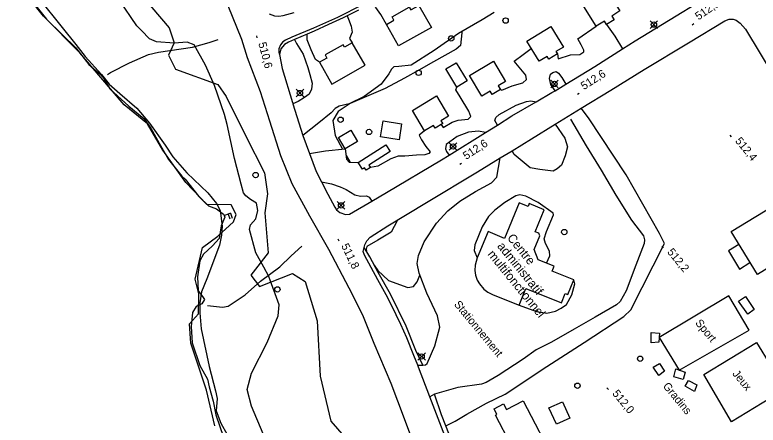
# Model space of a CAD drawing. Extents: x 347312 to 350503, y 6073086 to 6076432.
# Drawn here: x 348733 to 349011.5, y 6075010.1 to 6075163.9 of the extents above; entities that cross this region are included whole.
import ezdxf

# ---------------------------------------------------------------- set-up
doc = ezdxf.new("R2010")
doc.units = 0
for name, color, linetype in [('Level 1', 7, 'Continuous'), ('Level 19', 7, 'Continuous'), ('Level 2', 7, 'Continuous'), ('Level 21', 7, 'Continuous'), ('Level 22', 7, 'Continuous'), ('Level 26', 7, 'Continuous'), ('Level 3', 7, 'Continuous'), ('Level 31', 7, 'Continuous'), ('Level 36', 7, 'Continuous'), ('Level 37', 7, 'Continuous'), ('Level 4', 7, 'Continuous'), ('Level 44', 7, 'Continuous'), ('Level 52', 7, 'Continuous'), ('Level 56', 7, 'Continuous')]:
    doc.layers.add(name, color=color, linetype=linetype)

msp = doc.modelspace()

# ---------------------------------------------------------------- linework, layer by layer
at = {"layer": 'Level 1'}
for points in [[(348778.77, 6075159.8), (348765.55, 6075179.35)], [(348828.23, 6075065.76), (348826.31, 6075069.28), (348823.3, 6075074.72), (348820.99, 6075083.43), (348821.36, 6075085.16), (348823.3, 6075087.37), (348824.01, 6075090.6), (348823.55, 6075093.24), (348821.36, 6075094.6), (348819.6, 6075096.09), (348818.71, 6075097.18)], [(348826.08, 6075006.84), (348821.74, 6075017.15), (348820.1, 6075023.49), (348821.66, 6075029.61), (348827.51, 6075041.09), (348831.74, 6075051.08), (348832.12, 6075055.17), (348830.6, 6075059.27), (348828.86, 6075064.09), (348828.23, 6075065.76)]]:
    msp.add_lwpolyline(points, dxfattribs=at)
at = {"layer": 'Level 19'}
for points in [[(348872.23, 6075160.3), (348870.1, 6075163.96), (348868.29, 6075166.68), (348867.06, 6075168.92)], [(348912.62, 6075164.78), (348908.07, 6075162), (348899.31, 6075156.86), (348890.18, 6075150.51), (348881.47, 6075145.03), (348876.96, 6075144.47), (348875.05, 6075144.32), (348874.19, 6075143.54), (348873.21, 6075141.82), (348870.33, 6075137.93), (348863.92, 6075133.23), (348858.26, 6075130.51), (348854.59, 6075129.58), (348853.03, 6075128.74), (348851.52, 6075127.11), (348846.89, 6075123.43), (348840.91, 6075118.69)], [(348857.49, 6075163.46), (348858.02, 6075162.19), (348858.98, 6075159.59), (348859.44, 6075157.4), (348858.43, 6075154.99), (348859.47, 6075153.39)], [(348936.3, 6075149.2), (348936.56, 6075147.38), (348941.2, 6075148.88), (348944.68, 6075149.04), (348946.17, 6075150.05), (348946.27, 6075150.66), (348945.2, 6075152.68), (348943.98, 6075154.88), (348950.86, 6075159.6)], [(348954.74, 6075160.2), (348957.85, 6075155.91), (348960.72, 6075151.15)], [(348847.14, 6075146.1), (348845.71, 6075147.18), (348844.02, 6075150.75), (348842.55, 6075154.51), (348842.5, 6075156.63)], [(348837.79, 6075154.59), (348838.57, 6075153.13), (348841.05, 6075149.15), (348842.81, 6075144.13), (348843.59, 6075141.47), (348844.45, 6075138.26), (348844.16, 6075136.06), (348843.25, 6075134.17), (348841.56, 6075132.85), (348839.23, 6075131.38), (348837.2, 6075130.49)], [(348914.95, 6075135.93), (348915.52, 6075135.64), (348919.42, 6075137.29), (348923.4, 6075138.4), (348924.68, 6075139.64), (348924.5, 6075141.22), (348920.08, 6075146.53), (348923.43, 6075148.99), (348926.5, 6075151.27)], [(348935.45, 6075135.43), (348933.89, 6075137.76), (348933.32, 6075139.99), (348933.71, 6075141.6), (348934.6, 6075142.26), (348935.86, 6075142.58), (348936.77, 6075142.04), (348937.95, 6075140.34), (348939.43, 6075137.86)], [(348892.82, 6075122.77), (348893.56, 6075121.68), (348896.89, 6075123.63), (348899.15, 6075124.37), (348902.86, 6075124.8), (348903.84, 6075125.83), (348903.12, 6075127.79), (348899.9, 6075133.11), (348898.25, 6075135.81), (348898.64, 6075136.81)], [(348913.85, 6075122.58), (348912.93, 6075124.23), (348913.25, 6075125.39), (348914.54, 6075126.46), (348920.82, 6075130.07), (348924.69, 6075131.39), (348926.32, 6075131.61), (348928.37, 6075131.28)], [(348941.21, 6075124.76), (348947.07, 6075114.72), (348952.72, 6075105.65), (348958.22, 6075096.32), (348964.09, 6075086.91), (348968.55, 6075081), (348968.97, 6075079.59), (348968.89, 6075078.22), (348965.73, 6075070.09), (348962.06, 6075060.48), (348959.86, 6075056.39), (348958.4, 6075055.23), (348950.44, 6075050.58), (348942.58, 6075046.09), (348934.07, 6075041.2), (348928.4, 6075038.26), (348923.49, 6075034.88), (348914.12, 6075028.74), (348909.64, 6075026.1), (348907.93, 6075025.43), (348898.98, 6075024.24), (348890.29, 6075021.66), (348888.57, 6075020.68)], [(348886.55, 6075120.42), (348884.56, 6075118.74), (348885.43, 6075116.97), (348887.05, 6075114.48), (348888.6, 6075112.52), (348888.18, 6075111.94), (348886.64, 6075111.35), (348883.49, 6075111.23), (348879.09, 6075110.9), (348876.64, 6075110.86), (348873.95, 6075109.92), (348869.03, 6075107.13), (348866.3, 6075106.64)], [(348909.37, 6075119.76), (348906.78, 6075120.24), (348903.04, 6075119.93), (348898.76, 6075118.28), (348894.69, 6075115.29), (348894.37, 6075113.67), (348894.77, 6075112.65), (348895.71, 6075111.26)], [(348843.41, 6075111.92), (348849.46, 6075112.86), (348856.83, 6075113.61), (348857.27, 6075109.75), (348858.33, 6075108.67), (348861.65, 6075108.57)], [(348847.88, 6075101.3), (348851.62, 6075100.5), (348854.9, 6075099.37), (348857.16, 6075098.38), (348860.39, 6075096.41), (348862.57, 6075095.88), (348864.81, 6075096.08), (348865.8, 6075095.53), (348866.77, 6075094.04)]]:
    msp.add_lwpolyline(points, dxfattribs=at)
at = {"layer": 'Level 2'}
for points in [[(348742.17, 6075170.03), (348750.8, 6075159.12), (348755.85, 6075152.69), (348759.36, 6075148.3), (348765.53, 6075141.47), (348768.38, 6075137.87), (348772.33, 6075134.38), (348778.7, 6075128.92), (348783.53, 6075123.24), (348789.36, 6075115.08), (348792.21, 6075110.68), (348797.51, 6075104.6), (348805.28, 6075097.13), (348808.53, 6075093.2), (348809.95, 6075090.52), (348810.64, 6075084.72), (348810.4, 6075081.33), (348809.69, 6075077.55), (348804.99, 6075064.97), (348802.95, 6075060.07), (348802.28, 6075055.92), (348802.3, 6075052.21), (348802.83, 6075046.13), (348805.87, 6075032.06), (348808.22, 6075022.98), (348808.81, 6075020.02), (348808.47, 6075015.48)], [(348811.6, 6075126.53), (348807.82, 6075137.35), (348804.4, 6075145.01), (348800.15, 6075152.66), (348797.56, 6075153.68), (348792.74, 6075153.31), (348786.06, 6075153.81), (348783.47, 6075154.84), (348780.51, 6075158.04), (348778.77, 6075159.8)], [(348900.52, 6075157.57), (348900.52, 6075157.16), (348899.95, 6075152.32), (348898.38, 6075151.02)], [(348898.38, 6075151.02), (348889.86, 6075146.23), (348884.37, 6075143.12), (348879.06, 6075140.16), (348871.78, 6075136.32), (348858.63, 6075130.64), (348854.15, 6075127.61), (348852.19, 6075124.25), (348853.03, 6075118.62), (348855.83, 6075113.51)], [(348818.71, 6075097.18), (348817.77, 6075100.41), (348815.36, 6075110.03), (348812.62, 6075122.77), (348811.6, 6075126.53)], [(348857.11, 6075111.18), (348857.12, 6075111.16), (348858.55, 6075108.8), (348858.66, 6075108.66)], [(348876.24, 6075086.84), (348876.31, 6075086.71), (348874.01, 6075082.4), (348869.08, 6075079.45), (348864.94, 6075077.08), (348864.6, 6075076.04), (348864.74, 6075075.26)], [(348867.68, 6075070.11), (348869.01, 6075068.01), (348873.08, 6075064.3), (348880.27, 6075061.72), (348882.36, 6075062.02), (348883.76, 6075063.78), (348884.81, 6075066.29)], [(348808.47, 6075015.48), (348810.2, 6075010.82), (348812.63, 6075006.61)]]:
    msp.add_lwpolyline(points, dxfattribs=at)
at = {"layer": 'Level 21'}
for points in [[(348853.52, 6075090.81), (348854.82, 6075089.78), (348856.9, 6075089.09), (348858.39, 6075089.12), (348866.77, 6075094.04), (348872.22, 6075097.24), (348892.83, 6075109.47), (348895.71, 6075111.26), (348909.37, 6075119.76), (348913.85, 6075122.58), (348919.23, 6075125.96), (348928.37, 6075131.28), (348934.28, 6075134.71), (348935.45, 6075135.43), (348939.43, 6075137.86), (348950.29, 6075144.49), (348960.72, 6075151.15), (348965.46, 6075154.18), (348975.65, 6075160.34), (348993.33, 6075171.28)], [(348863.27, 6075167.65), (348853.96, 6075162.88), (348844.87, 6075158.83), (348836.81, 6075155.55), (348834.44, 6075154.42), (348833.42, 6075153.73), (348832.57, 6075152.57), (348831.98, 6075151.11), (348831.99, 6075149.83), (348832.15, 6075149.02), (348833.16, 6075143.79), (348837.02, 6075131.07), (348837.2, 6075130.49), (348840.91, 6075118.69), (348843.41, 6075111.92), (348845.92, 6075105.12), (348847.88, 6075101.3), (348850.29, 6075096.6), (348852.98, 6075091.73), (348853.52, 6075090.81)], [(348884.48, 6074997.74), (348878.97, 6075012.51), (348874.06, 6075025.65), (348867.61, 6075040.68), (348863.35, 6075051.26), (348858.3, 6075061.41), (348850.61, 6075075.93), (348843.56, 6075088.41), (348836.97, 6075100.59), (348832.69, 6075111), (348828.62, 6075123.98), (348825.02, 6075135.02), (348820.25, 6075147.74), (348818.09, 6075154.61), (348812.98, 6075167.19)], [(348828.34, 6075164.27), (348830.33, 6075163.51), (348831.89, 6075163.36), (348833.6, 6075163.57), (348837.63, 6075164.8)], [(348882.47, 6075036.22), (348879.92, 6075042.82), (348877.68, 6075047.82), (348875.87, 6075051.44), (348872.72, 6075057.84), (348868.98, 6075064.6), (348864.07, 6075073.84), (348863.56, 6075075.18), (348863.9, 6075076.62), (348864.14, 6075077.67), (348864.93, 6075079.18), (348866.2, 6075080.56), (348872.8, 6075084.76), (348887.23, 6075093.49), (348906.41, 6075105.08), (348914.85, 6075110.22), (348919.36, 6075112.96), (348926.61, 6075117.37), (348935.42, 6075122.84), (348940.32, 6075125.88), (348945.17, 6075128.84), (348956.28, 6075135.6), (348968.85, 6075143.38), (348985.46, 6075153.41), (348999.01, 6075161.56), (349000.73, 6075162.24), (349002.17, 6075162.23), (349003.35, 6075161.91), (349004.74, 6075160.78), (349006.74, 6075158.47), (349017.8, 6075140.24)], [(348894.15, 6075006.07), (348889.16, 6075019.13), (348888.57, 6075020.68), (348884.3, 6075031.85), (348884.01, 6075032.55), (348882.47, 6075036.22)]]:
    msp.add_lwpolyline(points, dxfattribs=at)
at = {"layer": 'Level 22'}
for points in [[(348861.83, 6075165.59), (348857.49, 6075163.46), (348855.99, 6075162.72), (348850.52, 6075160.23), (348845.22, 6075157.8), (348842.5, 6075156.63), (348837.79, 6075154.59), (348835.51, 6075153.61), (348834.03, 6075152.76), (348832.71, 6075151.07), (348832.15, 6075149.02)], [(348767.78, 6075141.51), (348768.84, 6075142.24), (348775.95, 6075145.86), (348783.11, 6075149.06), (348786.9, 6075149.94), (348799.62, 6075151.71), (348805.81, 6075153.52), (348809.18, 6075154.61)], [(348805.23, 6075054.95), (348810.79, 6075054.26), (348812.98, 6075054.71), (348819.32, 6075058.9), (348825.01, 6075064.06), (348832.36, 6075069.39), (348836.55, 6075073.61), (348840.6, 6075077.19)], [(348885.93, 6075032.62), (348883.24, 6075038.11), (348879.69, 6075047.18), (348873.78, 6075059.17), (348869.19, 6075067.29), (348866.04, 6075073.16), (348863.9, 6075076.62)], [(348910.09, 6074965.3), (348910.94, 6074966.09), (348907.59, 6074975.45), (348903.02, 6074987.55), (348897.65, 6075001.88), (348894.53, 6075009.85), (348892.91, 6075014), (348890.29, 6075021.66)]]:
    msp.add_lwpolyline(points, dxfattribs=at)
at = {"layer": 'Level 26'}
for p, q in [((348813.83, 6075089.52), (348812.9, 6075089.19)), ((348813.83, 6075089.52), (348814.44, 6075087.7)), ((348812.9, 6075089.19), (348813.53, 6075087.38))]:
    msp.add_line(p, q, dxfattribs=at)
at = {"layer": 'Level 3'}
for p, q in [((348986.78, 6075160.15), (348987.44, 6075160.6)), ((348823.52, 6075156.01), (348823.72, 6075155.24)), ((348943.81, 6075134.11), (348944.49, 6075134.54)), ((349000.93, 6075118.75), (349001.44, 6075118.13)), ((348899.71, 6075107.89), (348900.38, 6075108.33)), ((348854.01, 6075079.95), (348854.36, 6075079.23)), ((348975.47, 6075077.12), (348975.98, 6075076.5)), ((348954.9, 6075024.09), (348955.41, 6075023.47))]:
    msp.add_line(p, q, dxfattribs=at)
at = {"layer": 'Level 31'}
for points in [[(348946.2, 6075167.05), (348955.14, 6075172.65), (348959.73, 6075165.31), (348956.65, 6075163.39), (348957.55, 6075161.96), (348954.74, 6075160.2), (348953.91, 6075161.52), (348950.86, 6075159.6), (348946.2, 6075167.05)], [(348889.09, 6075159.12), (348876.81, 6075152.19), (348872.23, 6075160.3), (348875.03, 6075161.89), (348874.35, 6075163.1), (348880.81, 6075166.75), (348881.41, 6075165.7), (348884.42, 6075167.4), (348889.09, 6075159.12)], [(348924.85, 6075153.97), (348933.86, 6075159.47), (348938.55, 6075151.81), (348935.75, 6075150.1), (348936.3, 6075149.2), (348933.1, 6075147.24), (348932.44, 6075148.3), (348929.43, 6075146.46), (348924.85, 6075153.97)], [(348864.26, 6075144.95), (348859.47, 6075153.39), (348856.55, 6075151.73), (348856.02, 6075152.67), (348849.28, 6075148.84), (348849.94, 6075147.69), (348847.14, 6075146.1), (348851.81, 6075137.88), (348864.26, 6075144.95)], [(348898.64, 6075136.81), (348894.57, 6075143.6), (348898.43, 6075145.91), (348902.49, 6075139.12), (348898.64, 6075136.81)], [(348903.35, 6075141.14), (348912.4, 6075146.52), (348916.92, 6075138.93), (348914.15, 6075137.28), (348914.95, 6075135.93), (348911.82, 6075134.06), (348911.08, 6075135.3), (348907.94, 6075133.43), (348903.35, 6075141.14)], [(348881.96, 6075128.02), (348891.01, 6075133.48), (348895.57, 6075125.93), (348892.69, 6075124.2), (348893.36, 6075123.1), (348890.52, 6075121.38), (348889.88, 6075122.43), (348886.55, 6075120.42), (348881.96, 6075128.02)], [(348870.99, 6075124.16), (348877.96, 6075123.01), (348876.97, 6075117.01), (348870.01, 6075118.16), (348870.99, 6075124.16)], [(348854.29, 6075117.85), (348858.9, 6075120.61), (348861.44, 6075116.37), (348856.83, 6075113.61), (348854.29, 6075117.85)], [(348861.65, 6075108.57), (348872.01, 6075115.19), (348873.64, 6075112.64), (348865.7, 6075107.57), (348866.3, 6075106.64), (348864.67, 6075105.6), (348864.07, 6075106.55), (348863.26, 6075106.04), (348861.65, 6075108.57)], [(349032, 6075101.3), (349067.18, 6075043.47), (349040.89, 6075027.48), (349015.54, 6075069.14), (349011.24, 6075066.52), (349001.41, 6075082.69), (349032, 6075101.3)], [(348922.02, 6075055.07), (348924.46, 6075061.26), (348937.81, 6075055.99), (348939.17, 6075059.43), (348940.22, 6075059.01), (348942.42, 6075064.56), (348934.33, 6075067.76), (348935.1, 6075069.7), (348929.1, 6075072.07), (348927.66, 6075075.98), (348929.77, 6075081.06), (348929.36, 6075082), (348927.99, 6075082.57), (348931.38, 6075090.79), (348925.75, 6075093.12), (348925.32, 6075092.09), (348922.01, 6075093.46), (348916.49, 6075080.08), (348910.32, 6075082.62), (348906.29, 6075072.86), (348905.48, 6075070.03), (348905.39, 6075068.05), (348905.66, 6075066.28), (348906.29, 6075064.44), (348907.16, 6075063.03), (348908.73, 6075061.06), (348910.21, 6075059.89), (348912.27, 6075058.87), (348922.02, 6075055.07)], [(349006.75, 6075058.35), (349010.08, 6075053.44), (349007.66, 6075051.63), (349004.16, 6075056.55), (349006.75, 6075058.35)], [(348923.44, 6075019.16), (348935.55, 6074995.96), (348924.4, 6074990.14), (348918.11, 6075002.19), (348918.97, 6075002.64), (348913.13, 6075013.82), (348913.67, 6075014.11), (348912.57, 6075016.22), (348916.1, 6075018.06), (348917.22, 6075015.92), (348923.44, 6075019.16)], [(348935.93, 6075010.4), (348933.15, 6075016.54), (348938.18, 6075018.82), (348940.96, 6075012.68), (348935.93, 6075010.4)]]:
    msp.add_lwpolyline(points, dxfattribs=at)
at = {"layer": 'Level 36'}
for p, q in [((348971.06, 6075158.79), (348973.88, 6075161.61)), ((348971.06, 6075161.61), (348973.88, 6075158.79)), ((348933.81, 6075136.57), (348936.63, 6075139.39)), ((348933.81, 6075139.39), (348936.63, 6075136.57)), ((348838.44, 6075133.16), (348841.26, 6075135.98)), ((348838.44, 6075135.98), (348841.26, 6075133.16)), ((348895.79, 6075113.11), (348898.61, 6075115.93)), ((348895.79, 6075115.93), (348898.61, 6075113.11)), ((348853.85, 6075091.05), (348856.67, 6075093.87)), ((348853.85, 6075093.87), (348856.67, 6075091.05)), ((348884.02, 6075034.4), (348886.84, 6075037.22)), ((348884.02, 6075037.22), (348886.84, 6075034.4))]:
    msp.add_line(p, q, dxfattribs=at)
for centre in [(348916.93, 6075161.73), (348972.47, 6075160.2), (348896.55, 6075155.04), (348884.3, 6075142.12), (348935.22, 6075137.98), (348839.85, 6075134.57), (348855.06, 6075124.54), (348865.73, 6075119.96), (348897.2, 6075114.52), (348823.25, 6075103.84), (348855.26, 6075092.46), (348938.9, 6075082.47), (348831.39, 6075060.96), (348885.43, 6075035.81), (348967.33, 6075034.97), (348943.83, 6075024.87)]:
    msp.add_circle(centre, 1, dxfattribs=at)
at = {"layer": 'Level 37'}
msp.add_lwpolyline([(349004.36, 6075077.84), (349000.45, 6075075.4), (349004.61, 6075068.59), (349008.48, 6075071.07)], dxfattribs=at)
at = {"layer": 'Level 4'}
for points in [[(348737.03, 6075172.2), (348744.91, 6075162.26), (348750.7, 6075156.48), (348755.93, 6075151.45), (348760.69, 6075145.27), (348765.14, 6075141.55), (348766.32, 6075139.95), (348768.65, 6075136.14), (348775.73, 6075129.62), (348781.3, 6075125.01), (348783.94, 6075121.38), (348787.1, 6075115.75), (348790.62, 6075109.6), (348795.55, 6075103.4), (348796.89, 6075102.24), (348801.96, 6075095.78), (348805.64, 6075092.25), (348808.6, 6075091.15), (348811.19, 6075089.21), (348811.46, 6075088.62), (348811.71, 6075088.05), (348810.29, 6075084.76), (348809.64, 6075080.07), (348807.07, 6075077.26), (348803.72, 6075074.19), (348802.37, 6075071.63), (348801.52, 6075065.64), (348801.75, 6075060.46), (348803.28, 6075058.25), (348804.05, 6075057.22), (348803.11, 6075055.54), (348800.95, 6075054.58), (348799.63, 6075052.36), (348799.14, 6075047.03)], [(348811.46, 6075088.62), (348813.35, 6075089.37)], [(348799.14, 6075047.03), (348799.4, 6075040.9), (348802.3, 6075032.49), (348805.17, 6075027.3), (348805.86, 6075024.47), (348807.3, 6075019.08), (348808.35, 6075013.9), (348811.23, 6075005.62)]]:
    msp.add_lwpolyline(points, dxfattribs=at)
at = {"layer": 'Level 44'}
for points in [[(348807.93, 6075009.85), (348804.86, 6075023.18), (348798.98, 6075040.82), (348798.41, 6075048.06), (348801.81, 6075051.78), (348802.01, 6075059.35), (348800.62, 6075064.85), (348803.37, 6075076.64), (348809.14, 6075080.96), (348814.93, 6075086.35), (348815.92, 6075088.98), (348814.03, 6075092.71), (348804.95, 6075092.74), (348797.03, 6075100.99), (348788.41, 6075113.19), (348782.71, 6075122.97), (348774.03, 6075130.13), (348765.23, 6075140.36), (348757.34, 6075149.68), (348743.74, 6075163.33), (348733.03, 6075176.94)], [(348780.77, 6075170.93), (348790.88, 6075158.94), (348792.76, 6075153.41), (348790.59, 6075148.76), (348793.16, 6075143.49), (348809.13, 6075137.71), (348812.19, 6075133.3), (348819.41, 6075118.62), (348826.53, 6075104.61), (348827.71, 6075096.84), (348826.63, 6075089.61), (348827.89, 6075074.66), (348821.42, 6075066.29), (348824.65, 6075062.03), (348837.08, 6075066.87), (348841.84, 6075063.87), (348846.34, 6075049.19), (348847.4, 6075028.49), (348851.36, 6075011.55), (348859.73, 6075002.02)]]:
    msp.add_lwpolyline(points, dxfattribs=at)
at = {"layer": 'Level 52'}
for points in [[(348894.53, 6075009.85), (348898.03, 6075011.58), (348902.39, 6075014.27), (348909.8, 6075018.3), (348916.7, 6075021.67), (348932.32, 6075032.08), (348946.38, 6075041.05), (348961.17, 6075050.77), (348963.87, 6075053.36), (348976.39, 6075078.21), (348974.54, 6075081.87), (348962.09, 6075103.93), (348948, 6075125.23), (348945.17, 6075128.84)], [(348935.42, 6075122.84), (348939.12, 6075117.69), (348940.09, 6075114.43), (348939.18, 6075110.97), (348937.86, 6075107.55), (348936.29, 6075106.15), (348934.77, 6075105.25), (348929.73, 6075105.92), (348926.15, 6075106.58), (348920.15, 6075111.58), (348919.36, 6075112.96)], [(348884.01, 6075032.55), (348885.93, 6075032.62), (348886.88, 6075032.66), (348887.54, 6075033.14), (348890.41, 6075039.88), (348892.28, 6075046.83), (348891.43, 6075051.03), (348887.38, 6075059.6), (348884.52, 6075067.02), (348883.71, 6075070.64), (348884.33, 6075073.62), (348886.42, 6075078.85), (348891.02, 6075085.81), (348895.25, 6075090.47), (348899.77, 6075094.06), (348905.62, 6075097.69), (348911.65, 6075100.94), (348913.6, 6075102.97), (348914.85, 6075110.22)], [(348932.27, 6075070.82), (348933.53, 6075073.59), (348933.39, 6075075.31), (348931.89, 6075078.2), (348931.41, 6075079.87), (348932.27, 6075082.66), (348934.9, 6075088.88), (348934.75, 6075089.52), (348929.17, 6075093.57), (348924.44, 6075095.88), (348922.2, 6075096.37), (348920.69, 6075096.09), (348916.63, 6075093.5), (348912.91, 6075090.67), (348910.52, 6075088.35), (348908.13, 6075084.4), (348905.37, 6075077.61), (348905.11, 6075075.55), (348906.29, 6075072.86)], [(348922.02, 6075055.07), (348928.48, 6075052.7), (348932.35, 6075052.05), (348935.64, 6075052.84), (348937.68, 6075053.94), (348939.74, 6075055.3), (348941.7, 6075058.95), (348942.83, 6075063.05), (348942.42, 6075064.56)]]:
    msp.add_lwpolyline(points, dxfattribs=at)
at = {"layer": 'Level 56'}
for points in [[(348974.46, 6075042.97), (348981.96, 6075030.74), (349008.16, 6075045.66), (349000.53, 6075058.54), (348974.46, 6075042.97)], [(348971.46, 6075040.98), (348971.4, 6075044.77), (348974.53, 6075044.57), (348974.28, 6075041.22), (348971.46, 6075040.98)], [(349001.5, 6075011.38), (348991.19, 6075029.03), (349010.92, 6075041.09), (349021.61, 6075023.53), (349001.5, 6075011.38)], [(348974.31, 6075028.74), (348972.22, 6075031.88), (348974.56, 6075033.25), (348976.5, 6075030.29), (348974.31, 6075028.74)], [(348979.96, 6075028.23), (348980.7, 6075031.15), (348984.16, 6075030.01), (348983.43, 6075027.25), (348979.96, 6075028.23)], [(348987.63, 6075022.75), (348984.2, 6075024.68), (348985.5, 6075026.85), (348988.58, 6075025.24), (348987.63, 6075022.75)]]:
    msp.add_lwpolyline(points, dxfattribs=at)

# ---------------------------------------------------------------- texts
at = {"layer": 'Level 3'}
for s, rotation, p in [('512,9', 34.3038, (348989.18, 6075161.75)), ('510,6', 284.7859, (348824.22, 6075153.22)), ('512,6', 32.4407, (348946.26, 6075135.63)), ('512,6', 33.2876, (348902.14, 6075109.44)), ('512,4', 309.5679, (349002.74, 6075116.51)), ('511,8', 295.7148, (348855.23, 6075077.34)), ('512,2', 309.5679, (348977.28, 6075074.88)), ('512,0', 309.5679, (348956.71, 6075021.85))]:
    msp.add_text(s, height=3, rotation=rotation, dxfattribs=at).set_placement(p)
at = {"layer": 'Level 31'}
for s, p in [('Centre', (348917.3, 6075080.17)), ('administratif', (348913.58, 6075077.08)), ('multifonctionnel', (348909.96, 6075074.06))]:
    msp.add_text(s, height=3.33, rotation=309.1656, dxfattribs=at).set_placement(p)
at = {"layer": 'Level 52'}
msp.add_text('Stationnement', height=3, rotation=309.568, dxfattribs=at).set_placement((348897.4, 6075055.29))
at = {"layer": 'Level 56'}
for s, p in [('Sport', (348987.79, 6075048.3)), ('Jeux', (349001.71, 6075029.26)), ('Gradins', (348975.66, 6075024.63))]:
    msp.add_text(s, height=3, rotation=309.568, dxfattribs=at).set_placement(p)

doc.saveas('drawing.dxf')
